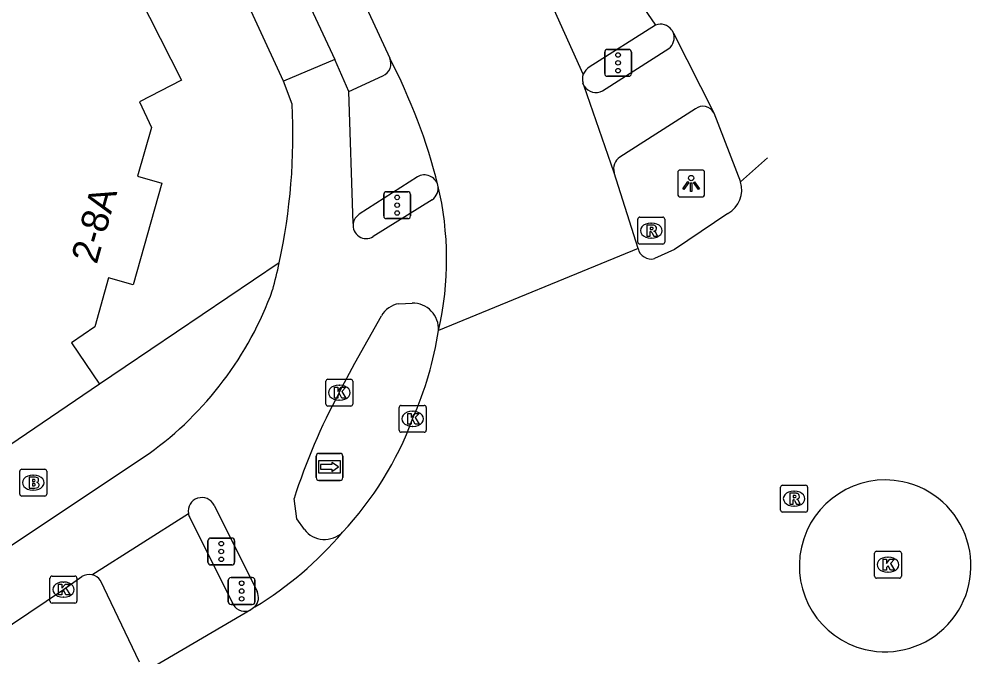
# Model space of a CAD drawing. Extents: x 161845 to 162341, y 381620 to 382158.
# Drawn here: x 162305.98 to 162341.31, y 381677.36 to 381701.04 of the extents above; entities that cross this region are included whole.
import ezdxf

# ---------------------------------------------------------------- set-up
doc = ezdxf.new("R2010")
doc.units = 0
for name, color, linetype in [('IMGEO_Brandkraan', 7, 'Continuous'), ('IMGEO_Fietspad_open', 7, 'Continuous'), ('IMGEO_Kolk', 7, 'Continuous'), ('IMGEO_Lichtpunt', 7, 'Continuous'), ('IMGEO_Pand', 7, 'Continuous'), ('IMGEO_Pand_nummerreeks', 7, 'Continuous'), ('IMGEO_Rijbaan_lokaal_gesloten', 7, 'Continuous'), ('IMGEO_Rijbaan_regionaal_gesloten', 7, 'Continuous'), ('IMGEO_Rioolput', 7, 'Continuous'), ('IMGEO_Verkeersregelinstallatiepaal', 7, 'Continuous'), ('IMGEO_Voetpad_gesloten', 7, 'Continuous'), ('IMGEO_Voetpad_open', 7, 'Continuous'), ('IMGEO_Wegwijzer', 7, 'Continuous')]:
    doc.layers.add(name, color=color, linetype=linetype)

msp = doc.modelspace()

# ---------------------------------------------------------------- linework, layer by layer
at = {"layer": 'IMGEO_Brandkraan'}
for p, q in [((162306.01, 381683.401), (162306.01, 381684.253)), ((162306.085, 381684.327), (162306.937, 381684.327)), ((162306.498, 381684.107), (162306.523, 381684.107)), ((162307.011, 381684.253), (162307.011, 381683.401)), ((162306.937, 381683.327), (162306.085, 381683.327)), ((162306.521, 381683.547), (162306.496, 381683.547))]:
    msp.add_line(p, q, dxfattribs=at)
for points in [[(162306.01, 381683.401), (162306.01, 381684.253)], [(162306.085, 381684.327), (162306.937, 381684.327)], [(162306.358, 381684.027), (162306.358, 381683.627), (162306.571, 381683.627)], [(162306.589, 381684.027), (162306.358, 381684.027)], [(162307.011, 381684.253), (162307.011, 381683.401)], [(162306.537, 381683.946), (162306.483, 381683.946), (162306.483, 381683.87)], [(162306.483, 381683.87), (162306.536, 381683.87)], [(162306.545, 381683.794), (162306.483, 381683.794), (162306.483, 381683.713)], [(162306.483, 381683.713), (162306.545, 381683.713)], [(162306.937, 381683.327), (162306.085, 381683.327)]]:
    msp.add_lwpolyline(points, dxfattribs=at)
for centre, radius, start, end in [((162306.087, 381684.251), 0.0765, 91.552, 178.448), ((162306.087, 381684.251), 0.0765, 91.552, 178.448), ((162306.593, 381683.882), 0.145, 59.4692, 91.5367), ((162306.935, 381684.251), 0.0765, 1.552, 88.448), ((162306.935, 381684.251), 0.0765, 1.552, 88.448), ((162306.538, 381683.908), 0.0379, 267.8285, 90.9355), ((162306.546, 381683.753), 0.0404, 269.8759, 90.5077), ((162306.618, 381683.929), 0.0922, 285.5137, 58.1501), ((162306.623, 381683.737), 0.105, 301.3115, 78.989), ((162306.087, 381683.403), 0.0765, 181.552, 268.448), ((162306.087, 381683.403), 0.0765, 181.552, 268.448), ((162306.577, 381683.878), 0.251, 268.6676, 293.5347), ((162306.935, 381683.403), 0.0765, 271.552, 358.448), ((162306.935, 381683.403), 0.0765, 271.552, 358.448)]:
    msp.add_arc(centre, radius, start, end, dxfattribs=at)
for centre, major_axis, ratio, start_param, end_param in [((162306.497, 381683.827), (-0.387, 0.002), 0.722429, 4.712389, 7.853982), ((162306.522, 381683.827), (-0.39, 0.002), 0.717154, 1.570796, 4.712389)]:
    msp.add_ellipse(centre, major_axis=major_axis, ratio=ratio, start_param=start_param, end_param=end_param, dxfattribs=at)
at = {"layer": 'IMGEO_Fietspad_open'}
for points in [[(162327.637, 381698.373), (162330.094, 381699.944)], [(162317.695, 381699.539), (162315.798, 381698.734)], [(162318.226, 381698.345), (162317.695, 381699.539)], [(162316.121, 381697.884), (162315.798, 381698.734)], [(162318.384, 381693.449), (162318.226, 381698.345)], [(162331.08, 381697.707), (162328.281, 381695.914)], [(162321.313, 381694.326), (162319.125, 381692.96)], [(162320.081, 381690.47), (162320.574, 381690.497)], [(162317.864, 381687.169), (162318.445, 381688.26), (162318.933, 381689.143), (162319.427, 381690.017)], [(162279.678, 381664.016), (162286.165, 381668.36), (162301.343, 381678.613), (162310.812, 381684.914)], [(162313.219, 381682.99), (162314.814, 381679.786)], [(162316.573, 381682.089), (162316.296, 381682.485), (162316.189, 381683.238)], [(162308.686, 381680.406), (162312.266, 381682.682)], [(162293.74, 381670.507), (162294.263, 381670.865), (162307.627, 381679.859), (162308.313, 381680.341)]]:
    msp.add_lwpolyline(points, dxfattribs=at)
for centre, radius, start, end in [((162329.789, 381700.346), 0.505, 307.2082, 19.0414), ((162327.386, 381698.806), 0.5, 210.6573, 300.0462), ((162293.525, 381696.773), 22.623, 347.7837, 2.8144), ((162331.356, 381697.339), 0.46, 27.9914, 126.8798), ((162328.553, 381695.487), 0.506, 122.4694, 197.5485), ((162320.985, 381694.769), 0.551, 306.4822, 10.5702), ((162318.867, 381693.375), 0.489, 171.2798, 301.877), ((162294.156, 381696.632), 21.977, 345.1018, 347.7945), ((162303.284, 381695.362), 12.877, 305.7717, 340.1147), ((162320.224, 381689.565), 0.916, 98.9778, 150.4398), ((162320.577, 381689.523), 0.974, 357.3695, 90.161), ((162337.855, 381676.328), 22.741, 151.5304, 162.3118), ((162312.765, 381682.768), 0.506, 26.0677, 189.7529), ((162317.323, 381682.671), 0.95, 217.8161, 313.9029), ((162308.582, 381679.902), 0.515, 78.2993, 121.4712), ((162314.363, 381679.561), 0.504, 317.4307, 26.4792)]:
    msp.add_arc(centre, radius, start, end, dxfattribs=at)
at = {"layer": 'IMGEO_Kolk'}
for p, q in [((162317.367, 381686.742), (162317.367, 381687.594)), ((162317.442, 381687.668), (162318.294, 381687.668)), ((162318.368, 381687.594), (162318.368, 381686.742)), ((162317.855, 381687.448), (162317.88, 381687.448)), ((162317.878, 381686.888), (162317.853, 381686.888)), ((162318.294, 381686.668), (162317.442, 381686.668)), ((162320.089, 381685.771), (162320.089, 381686.623)), ((162320.164, 381686.697), (162321.016, 381686.697)), ((162321.09, 381686.623), (162321.09, 381685.771)), ((162320.577, 381686.477), (162320.602, 381686.477)), ((162320.6, 381685.917), (162320.575, 381685.917)), ((162321.016, 381685.697), (162320.164, 381685.697)), ((162337.726, 381680.356), (162337.726, 381681.208)), ((162337.801, 381681.282), (162338.653, 381681.282)), ((162338.727, 381681.208), (162338.727, 381680.356)), ((162338.214, 381681.062), (162338.239, 381681.062)), ((162338.237, 381680.502), (162338.212, 381680.502)), ((162307.131, 381679.432), (162307.131, 381680.284)), ((162307.206, 381680.358), (162308.058, 381680.358)), ((162308.132, 381680.284), (162308.132, 381679.432)), ((162338.653, 381680.282), (162337.801, 381680.282)), ((162307.619, 381680.138), (162307.644, 381680.138)), ((162307.642, 381679.578), (162307.617, 381679.578)), ((162308.058, 381679.358), (162307.206, 381679.358))]:
    msp.add_line(p, q, dxfattribs=at)
for points in [[(162317.367, 381686.742), (162317.367, 381687.594)], [(162317.442, 381687.668), (162318.294, 381687.668)], [(162318.368, 381687.594), (162318.368, 381686.742)], [(162317.688, 381687.368), (162317.811, 381687.368), (162317.811, 381687.217), (162317.941, 381687.368), (162318.105, 381687.368), (162317.959, 381687.217), (162318.112, 381686.968), (162317.96, 381686.968), (162317.875, 381687.132), (162317.811, 381687.065), (162317.811, 381686.968), (162317.688, 381686.968), (162317.688, 381687.368)], [(162318.294, 381686.668), (162317.442, 381686.668)], [(162320.089, 381685.771), (162320.089, 381686.623)], [(162320.164, 381686.697), (162321.016, 381686.697)], [(162321.09, 381686.623), (162321.09, 381685.771)], [(162320.41, 381686.397), (162320.533, 381686.397), (162320.533, 381686.246), (162320.663, 381686.397), (162320.827, 381686.397), (162320.681, 381686.246), (162320.834, 381685.997), (162320.682, 381685.997), (162320.597, 381686.161), (162320.533, 381686.094), (162320.533, 381685.997), (162320.41, 381685.997), (162320.41, 381686.397)], [(162321.016, 381685.697), (162320.164, 381685.697)], [(162337.726, 381680.356), (162337.726, 381681.208)], [(162337.801, 381681.282), (162338.653, 381681.282)], [(162338.727, 381681.208), (162338.727, 381680.356)], [(162338.047, 381680.982), (162338.17, 381680.982), (162338.17, 381680.831), (162338.3, 381680.982), (162338.464, 381680.982), (162338.318, 381680.831), (162338.471, 381680.582), (162338.319, 381680.582), (162338.234, 381680.746), (162338.17, 381680.679), (162338.17, 381680.582), (162338.047, 381680.582), (162338.047, 381680.982)], [(162307.131, 381679.432), (162307.131, 381680.284)], [(162307.206, 381680.358), (162308.058, 381680.358)], [(162308.132, 381680.284), (162308.132, 381679.432)], [(162338.653, 381680.282), (162337.801, 381680.282)], [(162307.452, 381680.058), (162307.575, 381680.058), (162307.575, 381679.907), (162307.705, 381680.058), (162307.869, 381680.058), (162307.723, 381679.907), (162307.876, 381679.658), (162307.724, 381679.658), (162307.639, 381679.822), (162307.575, 381679.755), (162307.575, 381679.658), (162307.452, 381679.658), (162307.452, 381680.058)], [(162308.058, 381679.358), (162307.206, 381679.358)]]:
    msp.add_lwpolyline(points, dxfattribs=at)
for centre, start, end in [((162317.444, 381687.592), 91.552, 178.448), ((162317.444, 381687.592), 91.552, 178.448), ((162318.292, 381687.592), 1.552, 88.448), ((162318.292, 381687.592), 1.552, 88.448), ((162317.444, 381686.744), 181.552, 268.448), ((162317.444, 381686.744), 181.552, 268.448), ((162318.292, 381686.744), 271.552, 358.448), ((162318.292, 381686.744), 271.552, 358.448), ((162320.166, 381686.621), 91.552, 178.448), ((162320.166, 381686.621), 91.552, 178.448), ((162321.014, 381686.621), 1.552, 88.448), ((162321.014, 381686.621), 1.552, 88.448), ((162320.166, 381685.773), 181.552, 268.448), ((162320.166, 381685.773), 181.552, 268.448), ((162321.014, 381685.773), 271.552, 358.448), ((162321.014, 381685.773), 271.552, 358.448), ((162337.803, 381681.206), 91.552, 178.448), ((162337.803, 381681.206), 91.552, 178.448), ((162338.651, 381681.206), 1.552, 88.448), ((162338.651, 381681.206), 1.552, 88.448), ((162307.208, 381680.282), 91.552, 178.448), ((162307.208, 381680.282), 91.552, 178.448), ((162308.056, 381680.282), 1.552, 88.448), ((162308.056, 381680.282), 1.552, 88.448), ((162337.803, 381680.358), 181.552, 268.448), ((162337.803, 381680.358), 181.552, 268.448), ((162338.651, 381680.358), 271.552, 358.448), ((162338.651, 381680.358), 271.552, 358.448), ((162307.208, 381679.434), 181.552, 268.448), ((162307.208, 381679.434), 181.552, 268.448), ((162308.056, 381679.434), 271.552, 358.448), ((162308.056, 381679.434), 271.552, 358.448)]:
    msp.add_arc(centre, 0.0765, start, end, dxfattribs=at)
for centre, major_axis, ratio, start_param, end_param in [((162317.854, 381687.168), (-0.387, 0.002), 0.722429, 4.712389, 7.853982), ((162317.879, 381687.168), (-0.39, 0.002), 0.717154, 1.570796, 4.712389), ((162320.576, 381686.197), (-0.387, 0.002), 0.722429, 4.712389, 7.853982), ((162320.601, 381686.197), (-0.39, 0.002), 0.717154, 1.570796, 4.712389), ((162338.213, 381680.782), (-0.387, 0.002), 0.722429, 4.712389, 7.853982), ((162338.238, 381680.782), (-0.39, 0.002), 0.717154, 1.570796, 4.712389), ((162307.618, 381679.858), (-0.387, 0.002), 0.722429, 4.712389, 7.853982), ((162307.643, 381679.858), (-0.39, 0.002), 0.717154, 1.570796, 4.712389)]:
    msp.add_ellipse(centre, major_axis=major_axis, ratio=ratio, start_param=start_param, end_param=end_param, dxfattribs=at)
at = {"layer": 'IMGEO_Lichtpunt'}
for p, q in [((162330.423, 381695.338), (162330.423, 381694.531)), ((162330.423, 381695.338), (162330.423, 381694.531)), ((162331.325, 381695.433), (162330.517, 381695.433)), ((162331.325, 381695.433), (162330.517, 381695.433)), ((162331.419, 381694.531), (162331.419, 381695.338)), ((162331.419, 381694.531), (162331.419, 381695.338)), ((162330.517, 381694.437), (162331.325, 381694.437)), ((162330.517, 381694.437), (162331.325, 381694.437))]:
    msp.add_line(p, q, dxfattribs=at)
for points in [[(162330.797, 381695.002), (162330.836, 381694.974), (162330.648, 381694.712), (162330.61, 381694.739), (162330.797, 381695.002)], [(162331.009, 381694.974), (162331.047, 381695.001), (162331.234, 381694.739), (162331.195, 381694.711), (162331.009, 381694.974)], [(162330.899, 381694.954), (162330.946, 381694.954), (162330.946, 381694.632), (162330.899, 381694.632), (162330.899, 381694.954)]]:
    msp.add_lwpolyline(points, dxfattribs=at)
msp.add_circle((162330.922, 381695.136), 0.0994, dxfattribs=at)
for centre, start, end in [((162330.517, 381695.338), 90, 180), ((162330.517, 381695.338), 90, 180), ((162331.325, 381695.338), 0, 90), ((162331.325, 381695.338), 0, 90), ((162330.517, 381694.531), 180, 270), ((162330.517, 381694.531), 180, 270), ((162331.325, 381694.531), 270, 0), ((162331.325, 381694.531), 270, 360)]:
    msp.add_arc(centre, 0.0946, start, end, dxfattribs=at)
at = {"layer": 'IMGEO_Pand'}
for points in [[(162305.503, 381708.242), (162306.867, 381708.921), (162312.016, 381698.769), (162310.45, 381697.966), (162310.892, 381697.01), (162310.379, 381695.201), (162311.283, 381694.945), (162310.212, 381691.169), (162309.308, 381691.426), (162308.795, 381689.617), (162307.931, 381689.021), (162308.972, 381687.49)], [(162308.972, 381687.49), (162299.588, 381681.111)]]:
    msp.add_lwpolyline(points, dxfattribs=at)
at = {"layer": 'IMGEO_Rijbaan_lokaal_gesloten'}
for points in [[(162310.161, 381720.255), (162310.249, 381720.064), (162319.738, 381699.582)], [(162327.09, 381704.49), (162329.599, 381700.811)], [(162326.921, 381698.993), (162325.155, 381702.899)], [(162330.205, 381700.631), (162330.266, 381700.511)], [(162330.266, 381700.511), (162331.762, 381697.555)], [(162326.956, 381698.551), (162326.909, 381698.657)], [(162328.07, 381695.334), (162326.956, 381698.551)], [(162331.762, 381697.555), (162332.75, 381694.997)], [(162328.954, 381692.519), (162328.07, 381695.334)]]:
    msp.add_lwpolyline(points, dxfattribs=at)
for centre, radius, start, end in [((162329.789, 381700.34), 0.508, 34.9383, 111.9757), ((162300.507, 381689.585), 21.674, 14.1133, 27.4671), ((162327.387, 381698.808), 0.501, 158.3678, 197.5414), ((162309.989, 381692.125), 11.86, 347.1048, 13.384)]:
    msp.add_arc(centre, radius, start, end, dxfattribs=at)
at = {"layer": 'IMGEO_Rijbaan_regionaal_gesloten'}
for points in [[(162333.756, 381695.892), (162332.75, 381694.997)], [(162332.287, 381693.819), (162330.307, 381692.48), (162329.558, 381692.144)], [(162328.954, 381692.519), (162321.55, 381689.478)], [(162314.585, 381679.105), (162310.64, 381676.791), (162310.287, 381676.584)], [(162314.734, 381679.22), (162314.585, 381679.105)]]:
    msp.add_lwpolyline(points, dxfattribs=at)
for centre, radius, start, end in [((162331.795, 381694.692), 1.003, 299.4036, 17.6828), ((162329.44, 381692.628), 0.498, 192.6436, 283.6873), ((162308.384, 381691.56), 13.33, 336.2733, 351.0119), ((162308.954, 381690.484), 12.398, 316.735, 339.7695), ((162338.129, 381680.737), 3.192, 78.3521, 256.3624), ((162338.114, 381680.74), 3.192, 256.6365, 78.0781), ((162307.977, 381690.441), 13.099, 301.0544, 319.8015)]:
    msp.add_arc(centre, radius, start, end, dxfattribs=at)
at = {"layer": 'IMGEO_Rioolput'}
for p, q in [((162328.943, 381692.758), (162328.943, 381693.61)), ((162329.018, 381693.684), (162329.87, 381693.684)), ((162329.944, 381693.61), (162329.944, 381692.758)), ((162329.431, 381693.464), (162329.456, 381693.464)), ((162329.454, 381692.904), (162329.429, 381692.904)), ((162329.87, 381692.684), (162329.018, 381692.684)), ((162334.318, 381683.734), (162335.17, 381683.734)), ((162334.243, 381682.808), (162334.243, 381683.66)), ((162334.731, 381683.514), (162334.756, 381683.514)), ((162335.244, 381683.66), (162335.244, 381682.808)), ((162335.17, 381682.734), (162334.318, 381682.734)), ((162334.754, 381682.954), (162334.729, 381682.954))]:
    msp.add_line(p, q, dxfattribs=at)
for points in [[(162328.943, 381692.758), (162328.943, 381693.61)], [(162329.018, 381693.684), (162329.87, 381693.684)], [(162329.944, 381693.61), (162329.944, 381692.758)], [(162329.532, 381693.382), (162329.28, 381693.384), (162329.28, 381692.984)], [(162329.458, 381693.303), (162329.404, 381693.303), (162329.404, 381693.222)], [(162329.404, 381693.222), (162329.456, 381693.222)], [(162329.28, 381692.984), (162329.404, 381692.984), (162329.404, 381693.146), (162329.415, 381693.146)], [(162329.462, 381693.117), (162329.533, 381692.984), (162329.673, 381692.984), (162329.608, 381693.11)], [(162329.87, 381692.684), (162329.018, 381692.684)], [(162334.318, 381683.734), (162335.17, 381683.734)], [(162334.243, 381682.808), (162334.243, 381683.66)], [(162334.832, 381683.432), (162334.58, 381683.434), (162334.58, 381683.034)], [(162334.758, 381683.353), (162334.704, 381683.353), (162334.704, 381683.272)], [(162335.244, 381683.66), (162335.244, 381682.808)], [(162334.58, 381683.034), (162334.704, 381683.034), (162334.704, 381683.196), (162334.715, 381683.196)], [(162334.704, 381683.272), (162334.756, 381683.272)], [(162334.762, 381683.167), (162334.833, 381683.034), (162334.973, 381683.034), (162334.908, 381683.16)], [(162335.17, 381682.734), (162334.318, 381682.734)]]:
    msp.add_lwpolyline(points, dxfattribs=at)
for centre, radius, start, end in [((162329.02, 381693.608), 0.0765, 91.552, 178.448), ((162329.02, 381693.608), 0.0765, 91.552, 178.448), ((162329.868, 381693.608), 0.0765, 1.552, 88.448), ((162329.868, 381693.608), 0.0765, 1.552, 88.448), ((162329.44, 381693.411), 0.19, 274.7715, 282.9687), ((162329.464, 381693.207), 0.0964, 77.0061, 93.1865), ((162329.478, 381693.264), 0.0378, 276.6634, 79.6772), ((162329.531, 381693.272), 0.109, 350.3612, 89.416), ((162329.529, 381693.272), 0.112, 277.5842, 350.9817), ((162329.414, 381693.093), 0.0533, 26.0293, 88.6989), ((162329.513, 381693.057), 0.108, 29.5134, 73.7905), ((162329.02, 381692.76), 0.0765, 181.552, 268.448), ((162329.02, 381692.76), 0.0765, 181.552, 268.448), ((162329.868, 381692.76), 0.0765, 271.552, 358.448), ((162329.868, 381692.76), 0.0765, 271.552, 358.448), ((162334.32, 381683.658), 0.0765, 91.552, 178.448), ((162334.32, 381683.658), 0.0765, 91.552, 178.448), ((162335.168, 381683.658), 0.0765, 1.552, 88.448), ((162335.168, 381683.658), 0.0765, 1.552, 88.448), ((162334.764, 381683.257), 0.0964, 77.0061, 93.1865), ((162334.778, 381683.314), 0.0378, 276.6634, 79.6772), ((162334.831, 381683.322), 0.109, 350.3612, 89.416), ((162334.714, 381683.143), 0.0533, 26.0293, 88.6989), ((162334.74, 381683.461), 0.19, 274.7715, 282.9687), ((162334.829, 381683.322), 0.112, 277.5842, 350.9817), ((162334.813, 381683.107), 0.108, 29.5134, 73.7905), ((162334.32, 381682.81), 0.0765, 181.552, 268.448), ((162334.32, 381682.81), 0.0765, 181.552, 268.448), ((162335.168, 381682.81), 0.0765, 271.552, 358.448), ((162335.168, 381682.81), 0.0765, 271.552, 358.448)]:
    msp.add_arc(centre, radius, start, end, dxfattribs=at)
for centre, major_axis, ratio, start_param, end_param in [((162329.43, 381693.184), (-0.387, 0.002), 0.722429, 4.712389, 7.853982), ((162329.455, 381693.184), (-0.39, 0.002), 0.717154, 1.570796, 4.712389), ((162334.73, 381683.234), (-0.387, 0.002), 0.722429, 4.712389, 7.853982), ((162334.755, 381683.234), (-0.39, 0.002), 0.717154, 1.570796, 4.712389)]:
    msp.add_ellipse(centre, major_axis=major_axis, ratio=ratio, start_param=start_param, end_param=end_param, dxfattribs=at)
at = {"layer": 'IMGEO_Verkeersregelinstallatiepaal'}
for p, q in [((162327.717, 381699.012), (162327.717, 381699.812)), ((162327.717, 381699.812), (162327.717, 381699.012)), ((162327.817, 381699.912), (162328.607, 381699.912)), ((162328.607, 381699.912), (162327.817, 381699.912)), ((162328.707, 381699.812), (162328.707, 381699.012)), ((162328.707, 381699.012), (162328.707, 381699.812)), ((162328.607, 381698.912), (162327.817, 381698.912)), ((162327.817, 381698.912), (162328.607, 381698.912)), ((162319.617, 381694.628), (162320.407, 381694.628)), ((162320.407, 381694.628), (162319.617, 381694.628)), ((162319.517, 381693.728), (162319.517, 381694.528)), ((162319.517, 381694.528), (162319.517, 381693.728)), ((162320.507, 381694.528), (162320.507, 381693.728)), ((162320.507, 381693.728), (162320.507, 381694.528)), ((162320.407, 381693.628), (162319.617, 381693.628)), ((162319.617, 381693.628), (162320.407, 381693.628)), ((162312.99, 381680.872), (162312.99, 381681.672)), ((162312.99, 381681.672), (162312.99, 381680.872)), ((162313.09, 381681.772), (162313.88, 381681.772)), ((162313.88, 381681.772), (162313.09, 381681.772)), ((162313.98, 381681.672), (162313.98, 381680.872)), ((162313.98, 381680.872), (162313.98, 381681.672)), ((162313.88, 381680.772), (162313.09, 381680.772)), ((162313.09, 381680.772), (162313.88, 381680.772)), ((162313.748, 381679.403), (162313.748, 381680.203)), ((162313.748, 381680.203), (162313.748, 381679.403)), ((162313.848, 381680.303), (162314.638, 381680.303)), ((162314.638, 381680.303), (162313.848, 381680.303)), ((162314.738, 381680.203), (162314.738, 381679.403)), ((162314.738, 381679.403), (162314.738, 381680.203)), ((162314.638, 381679.303), (162313.848, 381679.303)), ((162313.848, 381679.303), (162314.638, 381679.303))]:
    msp.add_line(p, q, dxfattribs=at)
for centre in [(162328.212, 381699.702), (162328.212, 381699.412), (162328.212, 381699.122), (162320.012, 381694.418), (162320.012, 381694.128), (162320.012, 381693.838), (162313.485, 381681.562), (162313.485, 381681.272), (162313.485, 381680.982), (162314.243, 381680.093), (162314.243, 381679.803), (162314.243, 381679.513)]:
    msp.add_circle(centre, 0.085, dxfattribs=at)
for centre, start, end in [((162327.817, 381699.812), 90, 180), ((162327.817, 381699.812), 90, 180), ((162328.607, 381699.812), 0, 90), ((162328.607, 381699.812), 360, 90), ((162327.817, 381699.012), 180, 270), ((162327.817, 381699.012), 180, 270), ((162328.607, 381699.012), 270, 0), ((162328.607, 381699.012), 270, 0), ((162319.617, 381694.528), 90, 180), ((162319.617, 381694.528), 90, 180), ((162320.407, 381694.528), 0, 90), ((162320.407, 381694.528), 360, 90), ((162319.617, 381693.728), 180, 270), ((162319.617, 381693.728), 180, 270), ((162320.407, 381693.728), 270, 0), ((162320.407, 381693.728), 270, 0), ((162313.09, 381681.672), 90, 180), ((162313.09, 381681.672), 90, 180), ((162313.88, 381681.672), 0, 90), ((162313.88, 381681.672), 360, 90), ((162313.09, 381680.872), 180, 270), ((162313.09, 381680.872), 180, 270), ((162313.88, 381680.872), 270, 0), ((162313.88, 381680.872), 270, 0), ((162313.848, 381680.203), 90, 180), ((162313.848, 381680.203), 90, 180), ((162314.638, 381680.203), 0, 90), ((162314.638, 381680.203), 360, 90), ((162313.848, 381679.403), 180, 270), ((162313.848, 381679.403), 180, 270), ((162314.638, 381679.403), 270, 0), ((162314.638, 381679.403), 270, 0)]:
    msp.add_arc(centre, 0.1, start, end, dxfattribs=at)
at = {"layer": 'IMGEO_Voetpad_gesloten'}
for points in [[(162312.521, 381710.633), (162317.695, 381699.539)], [(162315.798, 381698.734), (162310.756, 381709.646)]]:
    msp.add_lwpolyline(points, dxfattribs=at)
at = {"layer": 'IMGEO_Voetpad_open'}
for points in [[(162329.599, 381700.811), (162327.144, 381699.248)], [(162318.226, 381698.345), (162319.487, 381698.934)], [(162320.762, 381695.184), (162318.609, 381693.79)], [(162315.636, 381691.986), (162308.972, 381687.49)], [(162312.317, 381682.533), (162313.932, 381679.299)], [(162310.457, 381677.165), (162309.004, 381680.2)]]:
    msp.add_lwpolyline(points, dxfattribs=at)
for centre, radius, start, end in [((162319.293, 381699.382), 0.488, 293.3838, 24.2689), ((162327.384, 381698.813), 0.497, 118.8902, 158.7697), ((162321.019, 381694.721), 0.529, 16.3066, 119.0612), ((162318.867, 381693.375), 0.488, 121.8455, 171.3189), ((162312.804, 381682.783), 0.548, 190.6298, 207.1605), ((162308.584, 381679.9), 0.516, 35.5152, 78.6145), ((162314.364, 381679.558), 0.504, 210.9635, 295.9441)]:
    msp.add_arc(centre, radius, start, end, dxfattribs=at)
at = {"layer": 'IMGEO_Wegwijzer'}
for p, q in [((162317.007, 381684.013), (162317.007, 381684.813)), ((162317.007, 381684.813), (162317.007, 381684.013)), ((162317.107, 381684.913), (162317.897, 381684.913)), ((162317.897, 381684.913), (162317.107, 381684.913)), ((162317.997, 381684.813), (162317.997, 381684.013)), ((162317.997, 381684.013), (162317.997, 381684.813)), ((162317.897, 381683.913), (162317.107, 381683.913)), ((162317.107, 381683.913), (162317.897, 381683.913))]:
    msp.add_line(p, q, dxfattribs=at)
for points in [[(162317.108, 381684.645), (162317.896, 381684.645), (162317.896, 381684.181), (162317.108, 381684.181), (162317.108, 381684.645)], [(162317.173, 381684.497), (162317.173, 381684.413), (162317.173, 381684.329), (162317.584, 381684.329), (162317.584, 381684.246), (162317.831, 381684.413), (162317.584, 381684.58), (162317.584, 381684.497), (162317.173, 381684.497)]]:
    msp.add_lwpolyline(points, dxfattribs=at)
for centre, start, end in [((162317.107, 381684.813), 90, 180), ((162317.107, 381684.813), 90, 180), ((162317.897, 381684.813), 0, 90), ((162317.897, 381684.813), 360, 90), ((162317.107, 381684.013), 180, 270), ((162317.107, 381684.013), 180, 270), ((162317.897, 381684.013), 270, 0), ((162317.897, 381684.013), 270, 0)]:
    msp.add_arc(centre, 0.1, start, end, dxfattribs=at)

# ---------------------------------------------------------------- texts
at = {"layer": 'IMGEO_Pand_nummerreeks'}
msp.add_text('2-8A', height=1, rotation=74.1637, dxfattribs=at).set_placement((162308.863, 381691.909))

doc.saveas('drawing.dxf')
